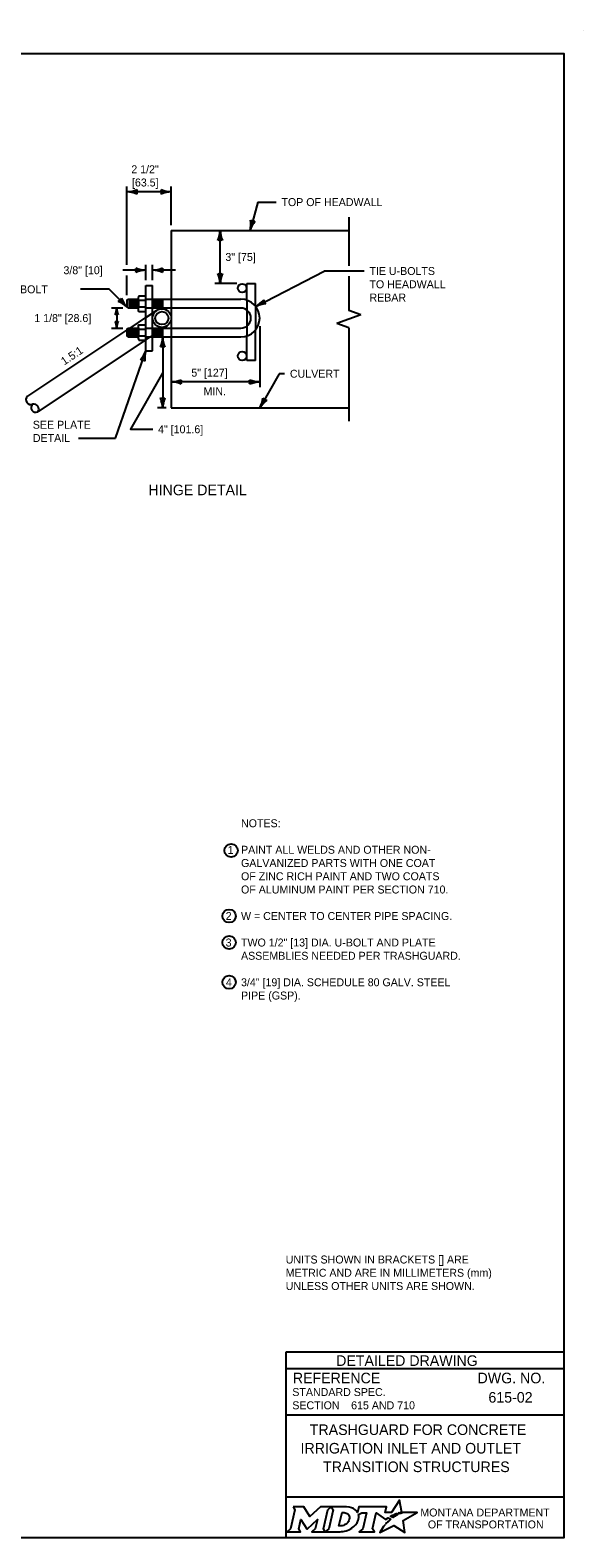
# Model space of a CAD drawing. Extents: x 49991.4 to 50021, y 49987.6 to 50011.4.
# Drawn here: x 50012.72 to 50016.9, y 49987.8 to 49999.18 of the extents above; entities that cross this region are included whole.
import ezdxf

# ---------------------------------------------------------------- set-up
doc = ezdxf.new("R2010")
doc.units = 0
for name, color, linetype in [('Default', 7, 'Continuous'), ('Level 1', 7, 'Continuous'), ('Level 2', 7, 'Continuous'), ('Level 3', 7, 'Continuous'), ('Level 4', 7, 'Continuous'), ('Level 5', 7, 'Continuous'), ('Level 6', 7, 'Continuous')]:
    doc.layers.add(name, color=color, linetype=linetype)

msp = doc.modelspace()

# ---------------------------------------------------------------- linework, layer by layer
at = {"layer": 'Default'}
for points in [[(50015.513, 49987.981), (50015.502, 49987.987), (50015.514, 49987.99), (50015.526, 49987.991), (50015.508, 49988.082), (50015.449, 49987.99), (50015.401, 49987.99), (50015.412, 49988.034), (50015.202, 49988.034), (50015.192, 49987.991), (50015.186, 49988)], [(50014.706, 49988.034), (50014.72, 49988.01), (50014.686, 49987.867), (50014.66, 49987.845), (50014.762, 49987.845), (50014.749, 49987.867), (50014.765, 49987.937), (50014.809, 49987.868), (50014.814, 49987.868), (50014.889, 49987.938), (50014.872, 49987.867), (50014.848, 49987.845), (50014.949, 49987.845), (50014.936, 49987.868), (50014.969, 49988.011)], [(50014.969, 49988.011), (50014.994, 49988.034), (50014.912, 49988.034), (50014.832, 49987.961), (50014.788, 49988.034), (50014.706, 49988.034)], [(50015.108, 49988.034), (50014.994, 49988.034), (50015.009, 49988.011), (50014.975, 49987.867), (50014.949, 49987.845), (50015.06, 49987.845)], [(50015.132, 49987.947), (50015.13, 49987.939), (50015.127, 49987.93), (50015.123, 49987.922), (50015.118, 49987.914), (50015.111, 49987.907), (50015.103, 49987.901), (50015.095, 49987.896), (50015.086, 49987.892), (50015.077, 49987.89), (50015.067, 49987.889), (50015.052, 49987.889), (50015.075, 49987.989), (50015.091, 49987.989), (50015.099, 49987.988), (50015.106, 49987.986), (50015.113, 49987.983), (50015.119, 49987.979), (50015.124, 49987.974), (50015.128, 49987.968), (50015.13, 49987.962), (50015.132, 49987.955), (50015.132, 49987.952), (50015.132, 49987.947)], [(50015.199, 49987.975), (50015.224, 49987.988), (50015.261, 49987.988), (50015.232, 49987.867), (50015.205, 49987.845), (50015.321, 49987.845), (50015.304, 49987.867), (50015.332, 49987.988), (50015.403, 49987.936), (50015.424, 49987.951), (50015.444, 49987.94)], [(50015.388, 49987.884), (50015.373, 49987.86), (50015.368, 49987.852), (50015.362, 49987.844), (50015.36, 49987.839), (50015.465, 49987.893), (50015.549, 49987.838), (50015.536, 49987.93), (50015.643, 49987.989), (50015.594, 49987.989), (50015.564, 49987.99), (50015.543, 49987.99), (50015.536, 49987.989), (50015.531, 49987.987), (50015.523, 49987.985), (50015.513, 49987.981)], [(50015.462, 49987.954), (50015.46, 49987.952), (50015.442, 49987.961), (50015.452, 49987.967), (50015.456, 49987.969), (50015.465, 49987.973), (50015.47, 49987.976), (50015.478, 49987.979), (50015.485, 49987.982), (50015.497, 49987.974), (50015.493, 49987.972), (50015.489, 49987.97), (50015.484, 49987.967), (50015.479, 49987.965), (50015.478, 49987.963), (50015.475, 49987.962), (50015.472, 49987.96), (50015.47, 49987.959), (50015.467, 49987.957), (50015.465, 49987.955), (50015.462, 49987.954)], [(50015.106, 49987.852), (50015.114, 49987.855), (50015.127, 49987.86), (50015.148, 49987.871)], [(50015.402, 49987.9), (50015.402, 49987.9)]]:
    msp.add_lwpolyline(points, dxfattribs=at)
for centre, radius, start, end in [((50015.087, 49987.973), 0.118, 300.9103, 339.1383), ((50015.131, 49987.955), 0.0709, 339.5329, 15.8582)]:
    msp.add_arc(centre, radius, start, end, dxfattribs=at)
for centre, major_axis, ratio, start_param, end_param in [((50015.106, 49987.986), (0.0834, -0.0037), 0.568097, 0.61298, 1.570796), ((50015.161, 49987.994), (0.0361, -0.0295), 0.469099, 1.225588, 1.570796), ((50015.433, 49987.93), (-0.0112, -0.0097), 0.021651, 3.157348, 6.283185), ((50015.06, 49987.993), (0, 0.148), 0.987302, 3.139398, 3.456847), ((50015.395, 49987.892), (-0.00694, -0.00806), 0.008222, 0, 3.137361), ((50015.412, 49987.911), (-0.0098, -0.0102), 0.016458, 3.141593, 6.279097)]:
    msp.add_ellipse(centre, major_axis=major_axis, ratio=ratio, start_param=start_param, end_param=end_param, dxfattribs=at)
at = {"layer": 'Level 1'}
for p, q in [((50016.9, 49999.176), (50016.9, 49999.176)), ((50013.786, 49997.665), (50015.126, 49997.665)), ((50013.786, 49997.665), (50013.786, 49996.325)), ((50014.356, 49997.138), (50014.356, 49997.263)), ((50014.356, 49997.263), (50014.423, 49997.263)), ((50014.423, 49997.092), (50014.423, 49997.263)), ((50013.452, 49997.137), (50013.46, 49997.146)), ((50013.46, 49997.146), (50013.537, 49997.146)), ((50013.46, 49997.079), (50013.46, 49997.146)), ((50013.485, 49997.146), (50013.485, 49997.079)), ((50013.51, 49997.146), (50013.51, 49997.079)), ((50013.535, 49997.146), (50013.535, 49997.079)), ((50013.537, 49997.076), (50013.537, 49997.149)), ((50013.542, 49997.171), (50013.595, 49997.171)), ((50013.595, 49996.756), (50013.595, 49997.25)), ((50013.595, 49997.25), (50013.645, 49997.25)), ((50013.595, 49997.053), (50013.595, 49997.171)), ((50013.645, 49996.756), (50013.645, 49997.25)), ((50013.645, 49997.146), (50014.312, 49997.146)), ((50013.671, 49997.146), (50013.671, 49997.079)), ((50013.696, 49997.146), (50013.696, 49997.079)), ((50013.721, 49997.146), (50013.721, 49997.079)), ((50013.452, 49997.137), (50013.452, 49997.087)), ((50013.46, 49997.079), (50013.452, 49997.087)), ((50013.46, 49997.079), (50013.537, 49997.079)), ((50013.473, 49997.137), (50013.473, 49997.087)), ((50013.498, 49997.137), (50013.498, 49997.087)), ((50013.523, 49997.137), (50013.523, 49997.087)), ((50013.541, 49997.137), (50013.595, 49997.137)), ((50013.541, 49997.087), (50013.595, 49997.087)), ((50013.541, 49997.053), (50013.595, 49997.053)), ((50013.645, 49997.079), (50014.312, 49997.079)), ((50013.645, 49997.041), (50013.677, 49997.062)), ((50013.658, 49997.138), (50013.658, 49997.088)), ((50013.683, 49997.138), (50013.683, 49997.088)), ((50013.708, 49997.138), (50013.708, 49997.088)), ((50014.356, 49997.064), (50014.356, 49996.942)), ((50013.452, 49996.919), (50013.46, 49996.928)), ((50013.452, 49996.919), (50013.452, 49996.869)), ((50013.46, 49996.928), (50013.537, 49996.928)), ((50013.46, 49996.861), (50013.46, 49996.928)), ((50013.472, 49996.869), (50013.472, 49996.919)), ((50013.476, 49996.928), (50013.595, 49997.008)), ((50013.485, 49996.861), (50013.485, 49996.928)), ((50013.497, 49996.869), (50013.497, 49996.919)), ((50013.523, 49996.869), (50013.523, 49996.919)), ((50013.535, 49996.861), (50013.535, 49996.928)), ((50013.537, 49996.857), (50013.537, 49996.931)), ((50013.541, 49996.953), (50013.595, 49996.953)), ((50013.541, 49996.919), (50013.595, 49996.919)), ((50013.595, 49996.836), (50013.595, 49996.953)), ((50013.645, 49996.928), (50014.312, 49996.928)), ((50013.645, 49996.928), (50013.645, 49996.861)), ((50013.658, 49996.92), (50013.658, 49996.87)), ((50013.671, 49996.928), (50013.671, 49996.861)), ((50013.683, 49996.92), (50013.683, 49996.87)), ((50013.696, 49996.928), (50013.696, 49996.861)), ((50013.708, 49996.92), (50013.708, 49996.87)), ((50013.721, 49996.928), (50013.721, 49996.861)), ((50013.729, 49996.928), (50013.755, 49996.945)), ((50014.423, 49996.684), (50014.423, 49996.915)), ((50012.703, 49996.413), (50013.452, 49996.912)), ((50012.781, 49996.296), (50013.591, 49996.836)), ((50013.46, 49996.861), (50013.452, 49996.869)), ((50013.46, 49996.861), (50013.537, 49996.861)), ((50013.541, 49996.869), (50013.595, 49996.869)), ((50013.542, 49996.836), (50013.595, 49996.836)), ((50013.645, 49996.861), (50014.312, 49996.861)), ((50014.356, 49996.684), (50014.356, 49996.868)), ((50013.595, 49996.756), (50013.645, 49996.756)), ((50014.423, 49996.684), (50014.356, 49996.684)), ((50013.786, 49996.325), (50015.126, 49996.325))]:
    msp.add_line(p, q, dxfattribs=at)
msp.add_lwpolyline([(49999.384, 49998.999), (50016.75, 49998.999), (50016.75, 49987.799), (49999.384, 49987.799)], close=True, dxfattribs=at)
msp.add_lwpolyline([(50013.51, 49996.861), (50013.51, 49996.928)], dxfattribs=at)
for centre, radius in [((50014.322, 49997.229), 0.0335), ((50013.716, 49997.003), 0.0703), ((50013.716, 49997.003), 0.0497), ((50014.322, 49996.717), 0.0335)]:
    msp.add_circle(centre, radius, dxfattribs=at)
for centre, radius, start, end in [((50013.566, 49997.154), 0.0293, 144.9118, 214.6543), ((50014.312, 49997.003), 0.142, 270, 90), ((50013.565, 49997.07), 0.0293, 145.0973, 214.827), ((50013.639, 49997.112), 0.1, 165.4182, 194.4042), ((50014.312, 49997.003), 0.0754, 270, 90), ((50013.566, 49996.936), 0.0293, 145.4375, 214.882), ((50013.639, 49996.894), 0.1, 165.4638, 194.4604), ((50013.566, 49996.852), 0.0293, 145.3427, 215.0628), ((50012.725, 49996.386), 0.0353, 130.1252, 297.1815), ((50012.764, 49996.327), 0.0353, 129.7836, 297.8932), ((50012.748, 49996.316), 0.0384, 327.9658, 99.4549)]:
    msp.add_arc(centre, radius, start, end, dxfattribs=at)
at = {"layer": 'Level 3'}
for p, q in [((50013.452, 49997.404), (50013.452, 49997.996)), ((50013.787, 49997.956), (50013.452, 49997.956)), ((50013.787, 49997.705), (50013.787, 49997.996)), ((50014.439, 49997.878), (50014.381, 49997.665)), ((50014.439, 49997.878), (50014.578, 49997.878)), ((50014.155, 49997.263), (50014.155, 49997.665)), ((50013.595, 49997.29), (50013.595, 49997.404)), ((50013.645, 49997.29), (50013.645, 49997.404)), ((50013.595, 49997.364), (50013.422, 49997.364)), ((50013.452, 49997.177), (50013.452, 49997.324)), ((50013.819, 49997.364), (50013.645, 49997.364)), ((50014.282, 49997.263), (50014.115, 49997.263)), ((50014.424, 49997.09), (50014.941, 49997.358)), ((50015.242, 49997.358), (50014.941, 49997.358)), ((50013.319, 49997.22), (50013.101, 49997.22)), ((50013.452, 49997.087), (50013.319, 49997.22)), ((50013.335, 49997.079), (50013.42, 49997.079)), ((50013.375, 49997.079), (50013.375, 49996.928)), ((50013.335, 49996.928), (50013.42, 49996.928)), ((50014.454, 49996.943), (50014.454, 49996.481)), ((50013.722, 49996.861), (50013.722, 49996.325)), ((50013.562, 49996.661), (50013.595, 49996.756)), ((50013.365, 49996.098), (50013.562, 49996.661)), ((50014.601, 49996.583), (50014.456, 49996.325)), ((50014.642, 49996.583), (50014.601, 49996.583)), ((50014.454, 49996.521), (50013.786, 49996.521)), ((50013.747, 49996.325), (50013.682, 49996.325)), ((50013.086, 49996.098), (50013.365, 49996.098))]:
    msp.add_line(p, q, dxfattribs=at)
msp.add_lwpolyline([(50013.722, 49996.593), (50013.479, 49996.164), (50013.647, 49996.164)], dxfattribs=at)
for centre in [(50014.238, 49992.985), (50014.223, 49992.491), (50014.223, 49992.291), (50014.223, 49991.991)]:
    msp.add_circle(centre, 0.05, dxfattribs=at)
for centre, radius, start, end in [((50013.44, 49998.188), 0.233, 272.8273, 292.0772), ((50013.442, 49997.733), 0.222, 67.456, 87.6395), ((50013.58, 49997.956), 0.0548, 162.1388, 197.8612), ((50013.796, 49998.178), 0.222, 247.456, 267.6395), ((50013.658, 49997.956), 0.0548, 342.1388, 17.8612), ((50013.798, 49997.723), 0.233, 92.8273, 112.0772), ((50014.154, 49997.714), 0.233, 347.7453, 6.9952), ((50014.593, 49997.598), 0.222, 142.374, 162.5575), ((50014.415, 49997.788), 0.0548, 237.0568, 272.7792), ((50013.933, 49997.674), 0.222, 337.456, 357.6395), ((50014.388, 49997.676), 0.233, 182.8273, 202.0772), ((50014.155, 49997.536), 0.0548, 72.1388, 107.8612), ((50013.604, 49997.586), 0.222, 247.456, 267.6395), ((50013.467, 49997.364), 0.0548, 342.1388, 17.8612), ((50013.634, 49997.597), 0.233, 272.8273, 292.0772), ((50013.774, 49997.364), 0.0548, 162.1388, 197.8612), ((50013.607, 49997.132), 0.233, 92.8273, 112.0772), ((50013.636, 49997.142), 0.222, 67.456, 87.6395), ((50014.155, 49997.391), 0.0548, 252.1388, 287.8612), ((50013.922, 49997.251), 0.233, 2.8273, 22.0772), ((50014.377, 49997.253), 0.222, 157.456, 177.6395), ((50013.361, 49997.178), 0.0548, 297.1232, 332.8456), ((50013.615, 49997.237), 0.222, 202.4404, 222.6239), ((50013.227, 49997.085), 0.148, 337.456, 357.6395), ((50013.375, 49996.993), 0.0365, 72.1388, 107.8612), ((50013.53, 49997.086), 0.155, 182.8273, 202.0772), ((50013.295, 49996.914), 0.233, 47.8117, 67.0616), ((50014.307, 49997.292), 0.233, 300.1569, 319.4067), ((50014.518, 49996.889), 0.222, 94.7856, 114.9691), ((50014.538, 49997.149), 0.0548, 189.4684, 225.1907), ((50013.375, 49997.013), 0.0365, 252.1388, 287.8612), ((50013.22, 49996.92), 0.155, 2.8273, 22.0772), ((50013.523, 49996.922), 0.148, 157.456, 177.6395), ((50013.5, 49996.87), 0.222, 337.456, 357.6395), ((50013.954, 49996.872), 0.233, 182.8273, 202.0772), ((50013.388, 49996.838), 0.222, 318.209, 338.3926), ((50013.553, 49996.635), 0.0548, 52.8919, 88.6142), ((50013.819, 49996.69), 0.233, 163.5804, 182.8302), ((50013.722, 49996.733), 0.0548, 72.1388, 107.8612), ((50013.775, 49996.754), 0.233, 272.8273, 292.0772), ((50013.777, 49996.299), 0.222, 67.456, 87.6395), ((50013.914, 49996.521), 0.0548, 162.1388, 197.8612), ((50014.463, 49996.743), 0.222, 247.456, 267.6395), ((50014.325, 49996.521), 0.0548, 342.1388, 17.8612), ((50014.465, 49996.288), 0.233, 92.8273, 112.0772), ((50013.722, 49996.453), 0.0548, 252.1388, 287.8612), ((50013.489, 49996.313), 0.233, 2.8273, 22.0772), ((50013.944, 49996.316), 0.222, 157.456, 177.6395), ((50014.246, 49996.426), 0.233, 334.3057, 353.5555), ((50014.647, 49996.211), 0.222, 128.9344, 149.1179), ((50014.518, 49996.437), 0.0548, 223.6172, 259.3396)]:
    msp.add_arc(centre, radius, start, end, dxfattribs=at)
at = {"layer": 'Level 4'}
for p, q in [((50013.595, 49997.146), (50013.645, 49997.146)), ((50013.595, 49997.079), (50013.645, 49997.079)), ((50013.595, 49997.008), (50013.645, 49997.041)), ((50014.356, 49997.138), (50014.356, 49997.064)), ((50014.423, 49997.092), (50014.423, 49996.915)), ((50013.591, 49996.836), (50013.729, 49996.928)), ((50013.595, 49996.928), (50013.645, 49996.928)), ((50014.356, 49996.942), (50014.356, 49996.868)), ((50013.595, 49996.861), (50013.645, 49996.861))]:
    msp.add_line(p, q, dxfattribs=at)
at = {"layer": 'Level 5'}
for p, q in [((50016.75, 49989.199), (50014.65, 49989.199)), ((50014.65, 49989.199), (50014.65, 49987.799)), ((50016.75, 49989.074), (50014.65, 49989.074)), ((50016.386, 49988.859), (50016.386, 49988.859)), ((50016.75, 49988.724), (50014.65, 49988.724)), ((50015.144, 49988.799), (50015.144, 49988.799)), ((50015.7, 49988.475), (50015.7, 49988.475)), ((50016.75, 49988.106), (50014.65, 49988.106))]:
    msp.add_line(p, q, dxfattribs=at)
at = {"layer": 'Level 6'}
for p, q in [((50015.126, 49997.765), (50015.126, 49997.398)), ((50015.126, 49997.318), (50015.126, 49997.06)), ((50015.218, 49997.027), (50015.126, 49997.06)), ((50015.218, 49997.027), (50015.126, 49996.995)), ((50015.126, 49996.995), (50015.035, 49996.962)), ((50015.126, 49996.93), (50015.035, 49996.962)), ((50015.126, 49996.93), (50015.126, 49996.225))]:
    msp.add_line(p, q, dxfattribs=at)

# ---------------------------------------------------------------- texts
at = {"layer": 'Default'}
for s, p in [('MONTANA DEPARTMENT', (50015.666, 49987.96)), ('OF TRANSPORTATION', (50015.723, 49987.87))]:
    msp.add_text(s, height=0.06, dxfattribs=at).set_placement(p)
at = {"layer": 'Level 2'}
for s, height, p in [('2 1/2"', 0.06, (50013.485, 49998.096)), ('[63.5]', 0.06, (50013.49, 49997.996)), ('TOP OF HEADWALL', 0.06, (50014.618, 49997.848)), ('3" [75]', 0.06, (50014.195, 49997.434)), ('3/8" [10]', 0.06, (50012.973, 49997.334)), ('TIE U-BOLTS', 0.06, (50015.282, 49997.328)), ('TO HEADWALL', 0.06, (50015.282, 49997.228)), ('1/2" [13] DIA. U-BOLT', 0.06, (50012.064, 49997.19)), ('REBAR', 0.06, (50015.282, 49997.128)), ('1 1/8" [28.6]', 0.06, (50012.753, 49996.973)), ('5" [127]', 0.06, (50013.938, 49996.561)), ('CULVERT', 0.06, (50014.682, 49996.553)), ('MIN.', 0.06, (50014.03, 49996.421)), ('SEE PLATE', 0.06, (50012.742, 49996.168)), ('DETAIL', 0.06, (50012.742, 49996.068)), ('4" [101.6]', 0.06, (50013.687, 49996.134)), ('HINGE DETAIL', 0.08, (50013.614, 49995.666)), ('NOTES:', 0.06, (50014.313, 49993.161)), ('1', 0.06, (50014.212, 49992.959)), ('PAINT ALL WELDS AND OTHER NON-', 0.06, (50014.313, 49992.961)), ('OF ZINC RICH PAINT AND TWO COATS', 0.06, (50014.313, 49992.761)), ('GALVANIZED PARTS WITH ONE COAT ', 0.06, (50014.313, 49992.861)), ('OF ALUMINUM PAINT PER SECTION 710.', 0.06, (50014.313, 49992.661)), ('2', 0.06, (50014.197, 49992.461)), ('W = CENTER TO CENTER PIPE SPACING.', 0.06, (50014.313, 49992.461)), ('3', 0.06, (50014.197, 49992.261)), ('TWO 1/2" [13] DIA. U-BOLT AND PLATE', 0.06, (50014.313, 49992.261)), ('ASSEMBLIES NEEDED PER TRASHGUARD.', 0.06, (50014.313, 49992.161)), ('3/4" [19] DIA. SCHEDULE 80 GALV. STEEL', 0.06, (50014.313, 49991.961)), ('4', 0.06, (50014.199, 49991.961)), ('PIPE (GSP).', 0.06, (50014.313, 49991.861)), ('UNITS SHOWN IN BRACKETS [] ARE ', 0.06, (50014.65, 49989.869)), ('METRIC AND ARE IN MILLIMETERS (mm) ', 0.06, (50014.65, 49989.769)), ('UNLESS OTHER UNITS ARE SHOWN.', 0.06, (50014.65, 49989.669)), ('615-02', 0.08, (50016.18, 49988.819)), ('615 AND 710', 0.06, (50015.144, 49988.769)), ('TRASHGUARD FOR CONCRETE', 0.08, (50014.832, 49988.575)), ('IRRIGATION INLET AND OUTLET', 0.08, (50014.762, 49988.435)), ('TRANSITION STRUCTURES', 0.08, (50014.932, 49988.295))]:
    msp.add_text(s, height=height, dxfattribs=at).set_placement(p)
msp.add_text('1.5:1', height=0.06, rotation=33.6653, dxfattribs=at).set_placement((50012.979, 49996.645))
at = {"layer": 'Level 5'}
for s, height, p in [('DETAILED DRAWING', 0.0799, (50015.031, 49989.096)), ('REFERENCE', 0.08, (50014.704, 49988.965)), ('DWG. NO.', 0.08, (50016.098, 49988.965)), ('STANDARD SPEC.', 0.06, (50014.7, 49988.869)), ('SECTION', 0.06, (50014.7, 49988.769))]:
    msp.add_text(s, height=height, dxfattribs=at).set_placement(p)

doc.saveas('drawing.dxf')
